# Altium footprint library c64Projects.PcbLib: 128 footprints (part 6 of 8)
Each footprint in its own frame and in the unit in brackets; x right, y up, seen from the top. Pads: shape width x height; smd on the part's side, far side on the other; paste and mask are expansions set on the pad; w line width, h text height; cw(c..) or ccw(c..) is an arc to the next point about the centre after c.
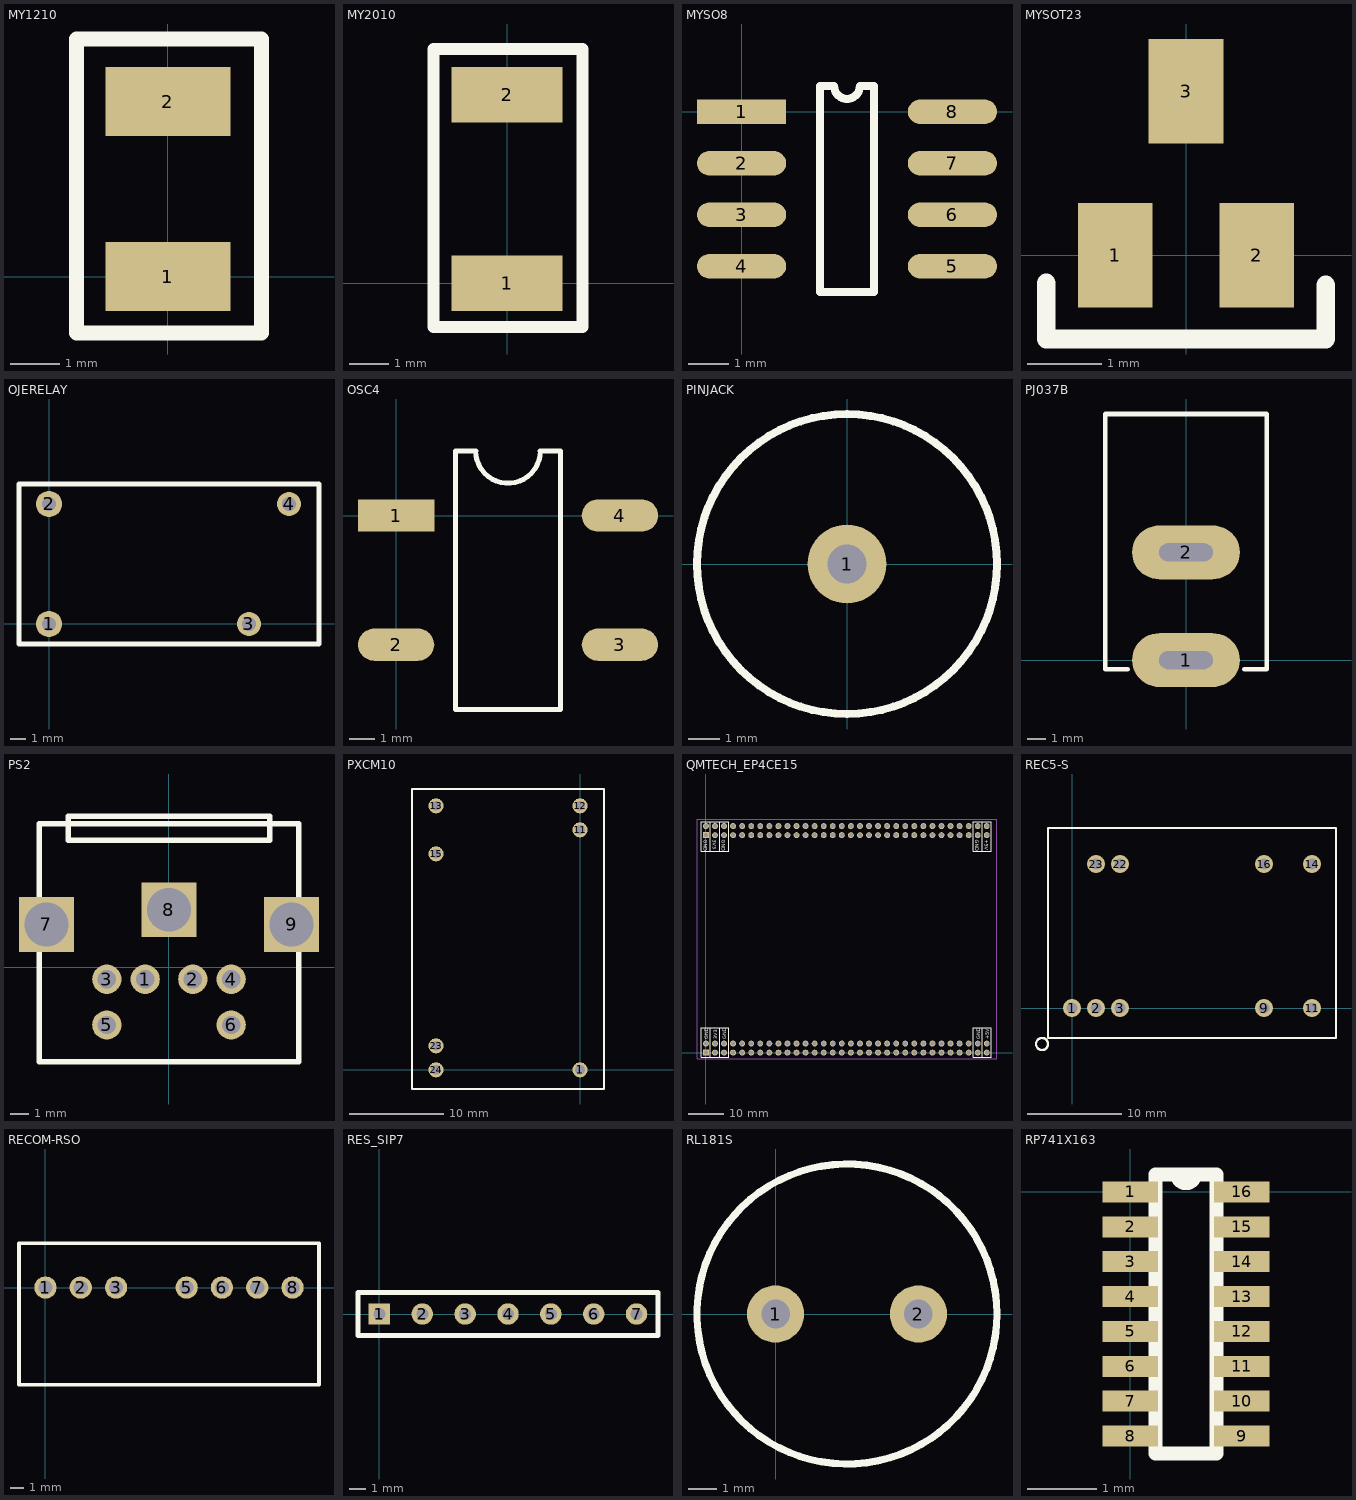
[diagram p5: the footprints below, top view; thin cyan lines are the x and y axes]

## MY1210 [mil]
pads (2):
  rect 100x55 smd: 1(0,0) 2(0,140)
Top Overlay:
  lines w12: -72.83,-45 -72.83,190 74.8,190 74.8,-45 -72.83,-45

## MY2010 [mm]
pads (2):
  rect 2.8x1.4 smd: 1(0,0) 2(0,4.75)
Top Overlay:
  lines w0.305: -1.85,-1.1 1.9,-1.1 1.9,5.9 -1.85,5.9 -1.85,-1.1

## MYSO8 [mm]
pads (8):
  rect 2.2x0.6 smd: 1(0,0)
  oval 2.2x0.6 smd: 2(0,-1.27) 3(0,-2.54) 4(0,-3.81) 5(5.2,-3.81) 6(5.2,-2.54) 7(5.2,-1.27) 8(5.2,0)
Top Overlay:
  lines w0.2: 1.935,-4.445 1.935,0.635 2.282,0.635 ccw(c2.6,0.635) 2.917,0.635 3.265,0.635 3.265,-4.445 1.935,-4.445

## MYSOT23 [mm]
pads (3):
  rect 1x1.4 smd: 1(-0.95,0) 2(0.95,0) 3(0,2.2)
Top Overlay:
  lines w0.254: -1.875,-0.375 -1.875,-1.125 1.875,-1.125 1.875,-0.4

## OJERELAY [mil]
pads (4):
  round 65 hole 35 mask+10: 1(0,0) 2(0,300)
  round 60 hole 35 mask+10: 3(500,0) 4(600,300)
Top Overlay:
  lines w12: -75,-50 675,-50 675,350 -75,350 -75,-50

## OSC4 [mm]
pads (4):
  rect 3x1.27 smd: 1(0,0)
  oval 3x1.27 smd: 2(0,-5.08) 3(8.8,-5.08) 4(8.8,0)
Top Overlay:
  lines w0.2: 2.335,-7.62 2.335,2.54 3.13,2.54 ccw(c4.4,2.54) 5.67,2.54 6.465,2.54 6.465,-7.62 2.335,-7.62

## PINJACK [mil]
pads (1):
  round 100 hole 50: 1(0,0)
Top Overlay:
  circle w10: c0,0 r190

## PJ037B [mm]
pads (2):
  oval 6x3 hole 1 slot 3 at 0 deg: 1(0,0) 2(0,6)
Top Overlay:
  lines w0.254: -3.25,-0.5 -4.5,-0.5 -4.5,13.7 4.5,13.7 4.5,-0.5 3.25,-0.5

## PS2 [mm]
pads (9):
  round 1.6 hole 1: 1(-1.3,-0.65) 2(1.3,-0.65) 3(-3.4,-0.65) 4(3.4,-0.65) 5(-3.4,-3.15) 6(3.4,-3.15)
  rect 3x3 hole 2.4: 7(-6.7,2.35) 8(0,3.15) 9(6.7,2.35)
Top Overlay:
  lines w0.305: -7.1,-5.15 -7.1,7.85 7.1,7.85 7.1,-5.15 -7.1,-5.15 ; -5.5,6.95 0,6.95 5.5,6.95 5.5,7.85 5.5,8.25 -5.5,8.25 -5.5,7.85 -5.5,6.95

## PXCM10 [mil]
pads (7):
  round 63 hole 40: 1(0,0) 11(0,1000) 12(0,1100) 13(-600,1100) 15(-600,900) 23(-600,100) 24(-600,0)
Top Overlay:
  lines w10: -700,-80 -700,1170 100,1170 100,-80 -700,-80

## QMTECH_EP4CE15 [mil]
pads (128):
  rect 65x65 hole 45: A1(0,2400) B1(0,0)
  round 65 hole 45: A2(0,2500) A3(100,2400) A4(100,2500) A5(200,2400) A6(200,2500) A7(300,2400) A8(300,2500) A9(400,2400) A10(400,2500) A11(500,2400) A12(500,2500) A13(600,2400) A14(600,2500) A15(700,2400) A16(700,2500) A17(800,2400) A18(800,2500) A19(900,2400) A20(900,2500) A21(1000,2400) A22(1000,2500) A23(1100,2400) A24(1100,2500) A25(1200,2400) A26(1200,2500) A27(1300,2400) A28(1300,2500) A29(1400,2400) A30(1400,2500) A31(1500,2400) A32(1500,2500) A33(1600,2400) A34(1600,2500) A35(1700,2400) A36(1700,2500) A37(1800,2400) A38(1800,2500) A39(1900,2400) A40(1900,2500) A41(2000,2400) A42(2000,2500) A43(2100,2400) A44(2100,2500) A45(2200,2400) A46(2200,2500) A47(2300,2400) A48(2300,2500) A49(2400,2400) A50(2400,2500) A51(2500,2400) A52(2500,2500) A53(2600,2400) A54(2600,2500) A55(2700,2400) A56(2700,2500) A57(2800,2400) A58(2800,2500) A59(2900,2400) A60(2900,2500) A61(3000,2400) A62(3000,2500) A63(3100,2400) A64(3100,2500) B2(0,100) B3(100,0) B4(100,100) B5(200,0) B6(200,100) B7(300,0) B8(300,100) B9(400,0) B10(400,100) B11(500,0) B12(500,100) B13(600,0) B14(600,100) B15(700,0) B16(700,100) B17(800,0) B18(800,100) B19(900,0) B20(900,100) B21(1000,0) B22(1000,100) B23(1100,0) B24(1100,100) B25(1200,0) B26(1200,100) B27(1300,0) B28(1300,100) B29(1400,0) B30(1400,100) B31(1500,0) B32(1500,100) B33(1600,0) B34(1600,100) B35(1700,0) B36(1700,100) B37(1800,0) B38(1800,100) B39(1900,0) B40(1900,100) B41(2000,0) B42(2000,100) B43(2100,0) B44(2100,100) B45(2200,0) B46(2200,100) B47(2300,0) B48(2300,100) B49(2400,0) B50(2400,100) B51(2500,0) B52(2500,100) B53(2600,0) B54(2600,100) B55(2700,0) B56(2700,100) B57(2800,0) B58(2800,100) B59(2900,0) B60(2900,100) B61(3000,0) B62(3000,100) B63(3100,0) B64(3100,100)
Top Overlay:
  lines w10: 50,-50 -50,-50 -50,150 -50,275 50,275 ; 50,-50 50,150 50,275 ; 50,-50 150,-50 ; 50,275 150,275 ; 50,2225 -50,2225 -50,2550 50,2550 ; 50,2225 150,2225 ; 50,2225 50,2550 ; 50,2550 150,2550 ; 150,-50 150,275 ; 150,-50 250,-50 250,275 150,275 ; 150,2225 150,2350 150,2550 ; 150,2225 250,2225 250,2350 250,2550 150,2550 ; 3050,-50 2950,-50 2950,150 2950,275 3050,275 ; 3050,-50 3050,275 ; 3050,-50 3150,-50 3150,275 3050,275 ; 3050,2225 2950,2225 2950,2550 3050,2550 ; 3050,2225 3150,2225 3150,2350 3150,2550 3050,2550 ; 3050,2225 3050,2550
  text "GND" at 3025,150 h40
  text "+5V" at 3125,150 h40
  text "+5V" at 3075,2350 h40
  text "GND" at 2975,2350 h40
  text "3V3" at 75,2350 h40
  text "GND" at -25,2350 h40
  text "GND" at 175,2350 h40
  text "GND" at 25,150 h40
  text "GND" at 225,150 h40
  text "3V3" at 125,150 h40
Mechanical 3:
  lines w10: -98.43,-66.93 -98.43,2574.8 3212.6,2574.8 3212.6,-66.93 -98.43,-66.93

## REC5-S [mil]
pads (9):
  round 75 hole 45: 1(0,0) 2(100,0) 3(200,0) 9(800,0) 11(1000,0) 14(1000,600) 16(800,600) 22(200,600) 23(100,600)
Top Overlay:
  circle w10: c-125,-150 r25
  lines w10: -100,-125 1100,-125 1100,750 -100,750 -100,-125

## RECOM-RSO [mil]
pads (7):
  round 63 hole 40 mask+10: 1(0,0) 2(100,0) 3(200,0) 5(400,0) 6(500,0) 7(600,0) 8(700,0)
Top Overlay:
  lines w10: -75,-275 775,-275 775,125 -75,125 -75,-275

## RES_SIP7 [mil]
pads (7):
  rect 50x50 hole 28: 1(0,0)
  round 50 hole 28: 2(100,0) 3(200,0) 4(300,0) 5(400,0) 6(500,0) 7(600,0)
Top Overlay:
  lines w12: -50,-50 -50,50 650,50 650,-50 -50,-50

## RL181S [mm]
pads (2):
  round 2 hole 1: 1(0,0) 2(5,0)
Top Overlay:
  circle w0.254: c2.5,0 r5.25
3D body: height 14, standoff 0, extent -2.75,-5.247 7.75,5.247

## RP741X163 [mm]
pads (16):
  rect 0.8x0.3 smd: 1(0,0) 2(0,-0.5) 3(0,-1) 4(0,-1.5) 5(0,-2) 6(0,-2.5) 7(0,-3) 8(0,-3.5) 9(1.6,-3.5) 10(1.6,-3) 11(1.6,-2.5) 12(1.6,-2) 13(1.6,-1.5) 14(1.6,-1) 15(1.6,-0.5) 16(1.6,0)
Top Overlay:
  lines w0.2: 0.365,-3.75 0.365,0.25 0.925,0.25 cw(c0.8,0.25) 0.675,0.25 1.235,0.25 1.235,-3.75 0.365,-3.75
